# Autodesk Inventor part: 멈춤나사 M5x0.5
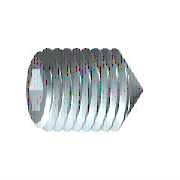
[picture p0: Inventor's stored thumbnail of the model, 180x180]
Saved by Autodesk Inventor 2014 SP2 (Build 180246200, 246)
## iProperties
Company: 한국ATC센터
IsCustomPart: 1
Created: 2014-10
Part Number: 멈춤나사 M5x0.5
Material: 강, 연강
Description: 6각 소켓 머리 없는 멈춤 나사
Document SubType Name: Modeling
Standard: KS B 1028
Designer: 한국ATC센터
Standards Organization: KS
Language: ko-KR
Size Designation: 원추점 M5x10
Categories: <MemberInstance><Categories><Category DisplayName="조임쇠" InternalName="e4da775c-781d-43d5-af7c-5136215cf5a6" Mnemonic="FSTN"><Category DisplayName="볼트" InternalN
Density: 7.86 g/cm^3
Mass: 1.16912 g
Surface Area: 1.91683 cm^2
Volume: 0.148743 cm^3
Appearance: 강철
Author: KYOUNG IL JANG
Revision Number: 1
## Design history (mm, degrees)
sketch "스케치1"
  geometry: L1 (0, 0)-(6.167, 0); L2 (10, 1.443)-(10, 2.5); L3 (10, 2.5)-(0, 2.5); L4 (10, 1.443)-(7, 1.443); L5 (7, 1.443)-(6.167, 0); L6 (0, -0.5)-(0, 3) reference; L7 (0, 2.5)-(0, 0)
  constraints: 13 end point, 3 parallel, 1 collinear, 1 perpendicular, 1 point on line
  dimensions: "d0" = 3 distance of L2.start L4.end (= INTI); "d1" = 60 deg angle of L5 L1; "d2" = 5 diameter of L3 L1 (= NND); "d3" = 2.88675 diameter of L4 L1 (= 1.1547 x SW); "d5" = 10 distance from line of L2 L3.end (= NLG)
revolve "본체" sketch "스케치1" stored, may be unused: angle "d6" = 90 deg
sketch "스케치2"
  geometry: L1 (-0.722, 1.25)-(0.722, 1.25); L2 (0.722, 1.25)-(1.443, 0); L3 (1.443, 0)-(0.722, -1.25); L4 (0.722, -1.25)-(-0.722, -1.25); L5 (-0.722, -1.25)-(-1.443, 0); L6 (-1.443, 0)-(-0.722, 1.25); 3 further points
  constraints: 12 end point, 1 coincident, 1 horizontal, 13 other
extrude "슬롯" join sketch "스케치2" taper "d7" = 0 deg; stored distance "d21" = 10
workaxis "Work Axis1"
workplane "Work Plane1"
body "Solid1"
feature "스레드" dims "d12" = 10 (= NLG), "d13" = 0
chamfer "모따기1" distance "d8" = 2.25 (computed from NND, SPD, FAWI); stored, may be unused: angle "d9" = 45 deg (= FAWI), second distance "d34" = 2.25 (computed from NND, SPD, FAWI)
chamfer "모따기2" distance "d10" = 0.49076 (= -0.5 x GD1 + 0.5 x NND); stored, may be unused: angle "d11" = 45 deg (= FAWI), second distance "d35" = 0.49076 (= -0.5 x GD1 + 0.5 x NND)
other parameters: "NND" = 5 [user parameter; used in 5 equation terms], "NLG" = 10 [user parameter; used in 2 equation terms], "INTI" = 3 [user parameter; used in 1 equation term], "FAWI" = 45 deg [user parameter; used in 4 equation terms], "SW" = 2.5 [user parameter; used in 2 equation terms], "GD1" = 4.01848 (= THREADDIA - 1.2269 x PTC) [user parameter; used in 2 equation terms], "d4" = 0, "FAWI1" = 45 deg [user parameter], "SPD" = 0.5 [user parameter; used in 2 equation terms], "d36" = 0, "d37" = 0, "GUL" = 0.49076 (= 0.61345 x PTC) [user parameter], "TPU" = 12.5 (computed from PTC) [user parameter], "TOA" = 30 deg [user parameter], "THREADDIA" = 5 [user parameter; used in 1 equation term], "PTC" = 0.8 [user parameter; used in 4 equation terms], "GAL" = 0.49076 (= 0.61345 x PTC) [user parameter], "E0" = 2.8875 (= 1.155 x SW) [user parameter]
